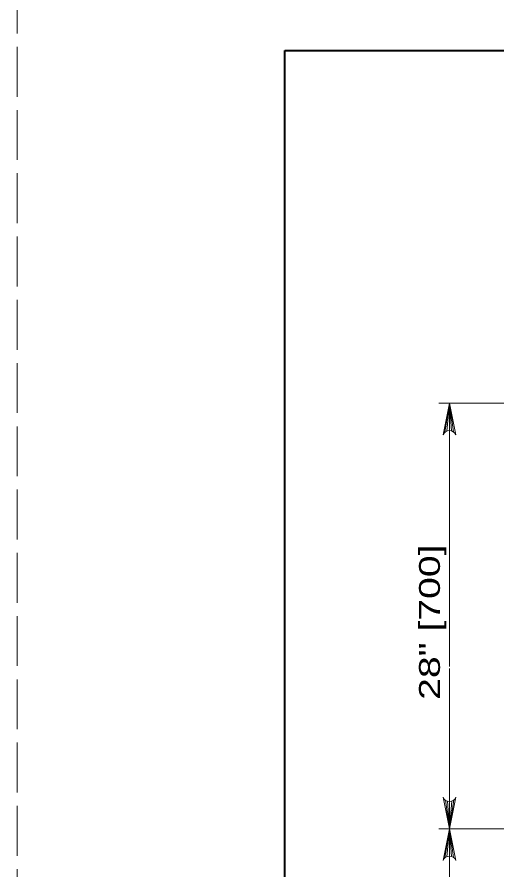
# Model space of a CAD drawing. Extents: x 339.1 to 373.1, y 1412.7 to 1456.7.
# Drawn here: x 339.06 to 342.65, y 1428.13 to 1434.5 of the extents above; entities that cross this region are included whole.
import ezdxf

# ---------------------------------------------------------------- set-up
doc = ezdxf.new("R2010")
doc.units = 0
doc.header["$LTSCALE"] = 0.062
doc.linetypes.add('LONG_DASHED', pattern=[7.5, 6, -1.5])
doc.layers.add('1', color=7, linetype='Continuous', lineweight=13)

msp = doc.modelspace()

# ---------------------------------------------------------------- linework, layer by layer
at = {"layer": '1', "lineweight": 25}
msp.add_line((341.0605, 1434.2455), (372.5605, 1434.2455), dxfattribs=at)
at = {"layer": '1'}
for p, q in [((344.76575, 1431.61425), (342.21133, 1431.61425)), ((342.257, 1431.39842), (342.29, 1431.61425)), ((342.27083, 1431.40658), (342.29, 1431.61425)), ((342.29, 1429.65067), (342.29, 1431.61425)), ((342.29, 1431.41033), (342.29, 1431.61425)), ((342.30508, 1431.40817), (342.29, 1431.61425)), ((342.31983, 1431.40092), (342.29, 1431.61425)), ((342.29, 1428.43842), (342.29, 1429.63525)), ((342.323, 1428.65417), (342.29, 1428.43842)), ((342.26017, 1428.65167), (342.29, 1428.43842)), ((342.27492, 1428.6445), (342.29, 1428.43842)), ((342.30917, 1428.646), (342.29, 1428.43842)), ((342.29, 1428.64225), (342.29, 1428.43842)), ((344.58483, 1428.43842), (342.21133, 1428.43842)), ((342.257, 1428.22258), (342.29, 1428.43842)), ((342.27083, 1428.23075), (342.29, 1428.43842)), ((342.29, 1428.43842), (342.29, 1427.08917)), ((342.29, 1428.23458), (342.29, 1428.43842)), ((342.30508, 1428.23233), (342.29, 1428.43842)), ((342.31983, 1428.22508), (342.29, 1428.43842))]:
    msp.add_line(p, q, dxfattribs=at)
at = {"layer": '1', "linetype": 'LONG_DASHED'}
msp.add_lwpolyline([(339.0605, 1412.7455), (373.0605, 1412.7455), (373.0605, 1434.7455), (339.0605, 1434.7455)], close=True, dxfattribs=at)
at = {"layer": '1', "lineweight": 25}
msp.add_lwpolyline([(372.5605, 1413.2455), (341.0605, 1413.2455), (341.0605, 1434.2455)], dxfattribs=at)
at = {"layer": '1', "lineweight": 40}
msp.add_lwpolyline([(341.0605, 1434.2455), (372.5605, 1434.2455), (372.5605, 1413.2455), (341.0605, 1413.2455)], close=True, dxfattribs=at)
at = {"layer": '1'}
for points in [[(342.24283, 1431.37867), (342.29, 1431.61425), (342.33708, 1431.37867)], [(342.33708, 1428.674), (342.29, 1428.43842), (342.24283, 1428.674)], [(342.24283, 1428.20283), (342.29, 1428.43842), (342.33708, 1428.20283)]]:
    msp.add_lwpolyline(points, dxfattribs=at)
for centre, start, end in [((342.29004, 1431.35961), 22.08782, 157.91395), ((342.28994, 1428.69302), 202.08782, 337.91395), ((342.29004, 1428.1838), 22.08782, 157.91395)]:
    msp.add_arc(centre, 0.05085, start, end, dxfattribs=at)

# ---------------------------------------------------------------- texts
at = {"layer": '1', "width": 1.4}
msp.add_text('28" [700]', height=0.156, rotation=90, dxfattribs=at).set_placement((342.21908, 1429.40083))

doc.saveas('drawing.dxf')
